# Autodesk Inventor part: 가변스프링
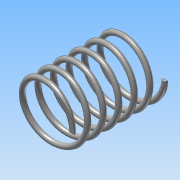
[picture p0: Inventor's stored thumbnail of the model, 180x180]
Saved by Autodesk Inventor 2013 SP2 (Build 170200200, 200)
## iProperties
Created: 2018-06
Part Number: 가변스프링
Material: 강철, 연강
Document SubType Name: Modeling
Designer: Administrator
Density: 7.86 g/cm^3
Mass: 83.1343 g
Surface Area: 106.475 cm^2
Volume: 10.5769 cm^3
Author: Administrator
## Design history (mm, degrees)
sketch "스케치1"
  geometry: L1 (0, 0)-(0, 73.25); L2 (0, 0)-(22.5, 0); L3 (0, 73.25)-(22.5, 73.25); C1 r 2 at (22.5, 0)
  constraints: 6 end point, 1 centre point, 1 coincident, 1 parallel, 1 perpendicular, 1 vertical
  dimensions: "d0" = 73.25 distance of L1.start L1.end (derived); "d1" = 22.5 distance of L1.start L2.end; "d2" = 22.5 distance of L1.end L3.end; "d3" = 4 diameter of C1
feature "코일1" sketch "스케치1" pitch "d4" = 10; turns "d6" = 6; dims "d5" = 73.25 (= d0), "d7" = 0, angle "d8" = 90 deg, angle "d9" = 90 deg, "d10" = 0, "d11" = 0
sketch "스케치2"
  geometry: L1 (0, 25)-(73.25, 25); L2 (73.25, 25)-(73.25, -25); L3 (73.25, -25)-(0, -25); L4 (0, -25)-(0, 25); 2 further points
  constraints: 8 end point, 2 parallel, 1 coincident, 1 horizontal, 1 midpoint, 1 perpendicular
  dimensions: "d12" = 73.25 distance of L1.start L1.end (derived); "d14" = 50 distance of L1.end L2.end
extrude "돌출1" sketch "스케치2" stored distance "d15" = 50; taper "d16" = 0 deg
node "솔리드1"
